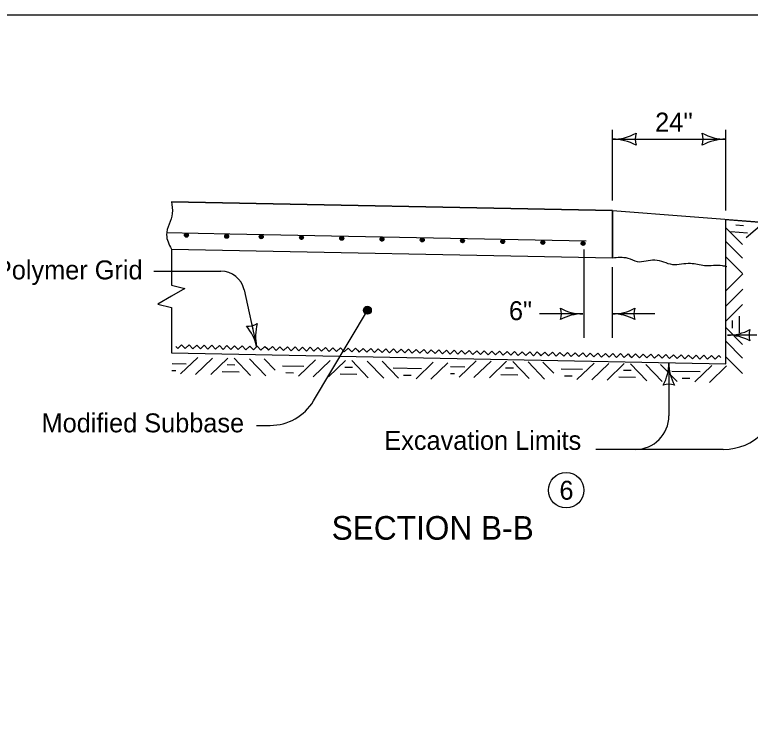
# Model space of a CAD drawing. Extents: x 9234 to 81668, y 5635 to 15999.
# Drawn here: x 18601 to 19223, y 9343 to 9944 of the extents above; entities that cross this region are included whole.
import ezdxf

# ---------------------------------------------------------------- set-up
doc = ezdxf.new("R2010")
doc.units = 0
for name, color, linetype in [('Level 61', 7, 'Continuous'), ('PS_CONST', 7, 'Continuous'), ('PS_DAWA', 7, 'Continuous'), ('PS_DIM', 7, 'Continuous'), ('PS_TEXT', 7, 'Continuous')]:
    doc.layers.add(name, color=color, linetype=linetype)

msp = doc.modelspace()

# ---------------------------------------------------------------- linework, layer by layer
at = {"layer": 'Level 61'}
msp.add_lwpolyline([(17332.52, 9944.02), (20467.53, 9944.02), (20467.53, 7924.02), (17332.52, 7924.02)], close=True, dxfattribs=at)
at = {"layer": 'PS_CONST'}
for p, q in [((18718.71, 9727.25), (18775.55, 9727.25)), ((18795.09, 9711.56), (18805.7, 9663.43)), ((18853.75, 9617.59), (18899.36, 9693.89)), ((19228.64, 9673.11), (19203.92, 9673.11)), ((19154.23, 9649.79), (19154.23, 9604.94)), ((18805.59, 9596.88), (18817.24, 9596.88)), ((19200.27, 9576.58), (19092.51, 9576.58))]:
    msp.add_line(p, q, dxfattribs=at)
msp.add_lwpolyline([(18899.08, 9691.17), (18900.2, 9691.67), (18901.94, 9692.21), (18902.27, 9693.97), (18902.03, 9695.52), (18900.92, 9696.95), (18899.27, 9696.8), (18897.53, 9696.56), (18896.69, 9695.17), (18896.54, 9693.7), (18897.57, 9691.79), (18898.84, 9691.63), (18900.58, 9692.08), (18902, 9693.18), (18901.96, 9694.84), (18900.85, 9696.17), (18899.29, 9696.31), (18897.54, 9695.97), (18897.28, 9695), (18896.93, 9693.82), (18897.75, 9692.38), (18899.01, 9692.42), (18900.47, 9692.65), (18901.51, 9693.46), (18900.98, 9694.91), (18899.89, 9695.75), (18898.43, 9695.8), (18898.06, 9695.02), (18897.6, 9694.13), (18898.31, 9692.98), (18899.39, 9692.72), (18900.35, 9693.23), (18900.42, 9694.3), (18899.91, 9695.07), (18898.93, 9695.33), (18898.45, 9694.93), (18898.18, 9694.34), (18898.69, 9693.48), (18899.38, 9693.3), (18900.04, 9693.71), (18899.93, 9694.29), (18899.43, 9694.67), (18898.76, 9694.64), (18898.77, 9694.16), (18899.36, 9693.89)], dxfattribs=at)
msp.add_circle((18899.34, 9694.21), 3.31, dxfattribs=at)
for centre, radius, start, end in [((18775.55, 9707.25), 20, 12.43134, 90), ((18798.45, 9696.33), 15.52, 264.68499, 300.15169), ((18766.46, 9654.79), 40.18, 12.41834, 40.49083), ((18844.93, 9672.07), 40.18, 164.34585, 192.41834), ((19203.92, 9713.29), 40.18, 270, 298.07249), ((19203.92, 9632.93), 40.18, 61.92751, 90), ((19237.6, 9673.11), 15.52, 162.26665, 197.73335), ((19114.05, 9649.79), 40.18, 331.92751, 360), ((19194.41, 9649.79), 40.18, 180, 208.07249), ((19154.23, 9616.11), 15.52, 72.26665, 107.73335), ((19200.28, 9623.84), 47.27, 270, 360), ((18817.24, 9639.42), 42.54, 270, 329.12488), ((19125.87, 9604.94), 28.36, 270, 360)]:
    msp.add_arc(centre, radius, start, end, dxfattribs=at)
at = {"layer": 'PS_DAWA'}
for p, q in [((19106.5, 9787.07), (19106.5, 9846.77)), ((19202.5, 9778.5), (19202.5, 9846.77)), ((19106.5, 9838.79), (19202.5, 9838.79)), ((19082.5, 9670.95), (19082.5, 9745.42)), ((19106.5, 9670.95), (19106.5, 9730.66)), ((19081.51, 9691.14), (19044.97, 9691.14)), ((19142.28, 9691.14), (19106.5, 9691.14))]:
    msp.add_line(p, q, dxfattribs=at)
for centre, radius, start, end in [((19106.5, 9881.29), 42.5, 270, 298.07249), ((19142.14, 9838.79), 16.42, 162.26665, 197.73335), ((19166.86, 9838.79), 16.42, 342.26665, 17.73335), ((19202.5, 9881.29), 42.5, 241.92751, 270), ((19106.5, 9796.29), 42.5, 61.92751, 90), ((19202.5, 9796.29), 42.5, 90, 118.07249), ((19047.82, 9691.14), 15.52, 342.26665, 17.73335), ((19081.51, 9731.31), 40.18, 241.92751, 270), ((19081.51, 9650.96), 40.18, 90, 118.07249), ((19106.5, 9731.31), 40.18, 270, 298.07249), ((19106.5, 9650.96), 40.18, 61.92751, 90), ((19140.19, 9691.14), 15.52, 162.26665, 197.73335)]:
    msp.add_arc(centre, radius, start, end, dxfattribs=at)
at = {"layer": 'PS_DIM'}
for p, q in [((19106.5, 9778.5), (18733.57, 9785.99)), ((18733.57, 9785.99), (19106.5, 9778.5)), ((19106.5, 9738.5), (19106.5, 9778.5)), ((19106.5, 9778.5), (19106.5, 9738.5)), ((19106.5, 9778.5), (19305.96, 9763.15)), ((19201.89, 9770.92), (19305.35, 9762.96)), ((19202.5, 9648.85), (19202.5, 9771.12)), ((19234.79, 9768.39), (19219.61, 9755.38)), ((18783.05, 9758.55), (18729.6, 9759.63)), ((19202.5, 9764.01), (19216.64, 9749.87)), ((19084.4, 9752.51), (18783.05, 9758.55)), ((19202.5, 9752.43), (19216.64, 9738.29)), ((18733.57, 9745.98), (19106.5, 9738.5)), ((18733.57, 9745.98), (19106.5, 9738.5)), ((18733.57, 9745.72), (18733.57, 9715.46)), ((19202.5, 9739.37), (19216.64, 9725.23)), ((19202.73, 9710.84), (19216.87, 9724.99)), ((18733.57, 9715.46), (18744.92, 9712.63)), ((18744.92, 9712.63), (18733.57, 9706.01)), ((19202.73, 9697.94), (19216.87, 9712.08)), ((18733.57, 9706.01), (18722.23, 9699.39)), ((18722.23, 9699.39), (18733.57, 9696.55)), ((18733.57, 9696.55), (18733.57, 9658.24)), ((19202.5, 9684.93), (19216.64, 9699.07)), ((18801.3, 9683.35), (18802.43, 9678.24)), ((19202.5, 9679.52), (19216.64, 9665.37)), ((19202.5, 9667.94), (19216.64, 9653.8)), ((18733.57, 9658.24), (19202.49, 9648.83)), ((18755.84, 9654.22), (18741.42, 9640.37)), ((18768.29, 9653.75), (18753.86, 9639.89)), ((18781.3, 9653.71), (18766.87, 9639.86)), ((18786.71, 9653.6), (18800.56, 9639.18)), ((18799.71, 9653.12), (18813.56, 9638.69)), ((18812.16, 9653.09), (18821.26, 9643.62)), ((19202.5, 9654.88), (19216.64, 9640.74)), ((18855.38, 9652.23), (18840.95, 9638.37)), ((18867.82, 9651.75), (18853.4, 9637.89)), ((18880.83, 9651.71), (18866.41, 9637.86)), ((18886.24, 9651.61), (18900.09, 9637.18)), ((18899.24, 9651.12), (18913.1, 9636.7)), ((18911.69, 9651.09), (18925.55, 9636.67)), ((18954.91, 9650.23), (18940.48, 9636.37)), ((18967.35, 9649.75), (18952.93, 9635.9)), ((18991.44, 9651.59), (18977.02, 9637.73)), ((19003.89, 9651.11), (18989.46, 9637.25)), ((19016.9, 9651.07), (19002.47, 9637.22)), ((19022.31, 9650.97), (19036.16, 9636.54)), ((19035.31, 9650.48), (19049.16, 9636.06)), ((19047.76, 9650.46), (19056.86, 9640.98)), ((19090.98, 9649.59), (19076.55, 9635.73)), ((19103.42, 9649.11), (19089, 9635.26)), ((19116.43, 9649.08), (19102.01, 9635.22)), ((19121.84, 9648.97), (19135.7, 9634.55)), ((19134.84, 9648.48), (19148.7, 9634.06)), ((19147.29, 9648.46), (19161.15, 9634.03)), ((19190.51, 9647.59), (19176.09, 9633.73)), ((19202.95, 9647.11), (19188.53, 9633.26))]:
    msp.add_line(p, q, dxfattribs=at)
for points in [[(19210.8, 9766.38), (19217.32, 9765.88)], [(18744.82, 9757.5), (18745.07, 9758.06), (18745.34, 9758.92), (18746.22, 9759.09), (18746.99, 9758.97), (18747.71, 9758.42), (18747.64, 9757.59), (18747.51, 9756.72), (18746.82, 9756.3), (18746.09, 9756.22), (18745.13, 9756.74), (18745.05, 9757.37), (18745.27, 9758.24), (18745.83, 9758.96), (18746.65, 9758.93), (18747.32, 9758.38), (18747.39, 9757.6), (18747.22, 9756.73), (18746.73, 9756.59), (18746.14, 9756.42), (18745.43, 9756.82), (18745.44, 9757.46), (18745.56, 9758.18), (18745.96, 9758.71), (18746.69, 9758.45), (18747.11, 9757.9), (18747.14, 9757.17), (18746.74, 9756.98), (18746.3, 9756.75), (18745.73, 9757.11), (18745.59, 9757.65), (18745.85, 9758.13), (18746.39, 9758.16), (18746.77, 9757.91), (18746.9, 9757.42), (18746.7, 9757.18), (18746.4, 9757.04), (18745.97, 9757.3), (18745.89, 9757.64), (18746.09, 9757.97), (18746.38, 9757.92), (18746.57, 9757.67), (18746.56, 9757.33), (18746.32, 9757.34), (18746.18, 9757.63)], [(19206.54, 9760.83), (19220.69, 9759.74)], [(18778.85, 9756.57), (18779.1, 9757.13), (18779.37, 9758), (18780.25, 9758.16), (18781.03, 9758.04), (18781.74, 9757.49), (18781.67, 9756.66), (18781.55, 9755.79), (18780.86, 9755.37), (18780.12, 9755.29), (18779.16, 9755.81), (18779.09, 9756.44), (18779.31, 9757.32), (18779.86, 9758.03), (18780.69, 9758), (18781.35, 9757.45), (18781.42, 9756.67), (18781.26, 9755.8), (18780.77, 9755.67), (18780.18, 9755.49), (18779.46, 9755.9), (18779.48, 9756.53), (18779.59, 9757.26), (18780, 9757.78), (18780.72, 9757.52), (18781.14, 9756.97), (18781.17, 9756.24), (18780.78, 9756.06), (18780.33, 9755.82), (18779.76, 9756.18), (18779.63, 9756.72), (18779.88, 9757.2), (18780.42, 9757.23), (18780.8, 9756.98), (18780.94, 9756.49), (18780.73, 9756.25), (18780.44, 9756.11), (18780.01, 9756.37), (18779.92, 9756.71), (18780.12, 9757.05), (18780.41, 9756.99), (18780.6, 9756.74), (18780.59, 9756.4), (18780.35, 9756.41), (18780.21, 9756.7)], [(18811.11, 9756.24), (18810.86, 9756.8), (18810.59, 9757.66), (18809.71, 9757.84), (18808.94, 9757.72), (18808.22, 9757.16), (18808.3, 9756.33), (18808.42, 9755.46), (18809.11, 9755.04), (18809.84, 9754.97), (18810.8, 9755.48), (18810.88, 9756.12), (18810.66, 9756.98), (18810.1, 9757.7), (18809.28, 9757.68), (18808.61, 9757.12), (18808.54, 9756.34), (18808.71, 9755.47), (18809.2, 9755.34), (18809.79, 9755.16), (18810.51, 9755.57), (18810.49, 9756.2), (18810.37, 9756.93), (18809.97, 9757.45), (18809.24, 9757.19), (18808.82, 9756.64), (18808.8, 9755.91), (18809.19, 9755.73), (18809.63, 9755.5), (18810.21, 9755.85), (18810.34, 9756.39), (18810.08, 9756.87), (18809.54, 9756.9), (18809.16, 9756.65), (18809.03, 9756.16), (18809.23, 9755.92), (18809.53, 9755.78), (18809.96, 9756.04), (18810.04, 9756.39), (18809.84, 9756.72), (18809.55, 9756.66), (18809.36, 9756.41), (18809.37, 9756.07), (18809.62, 9756.08), (18809.75, 9756.38)], [(18845.14, 9755.56), (18844.89, 9756.11), (18844.62, 9756.98), (18843.74, 9757.15), (18842.97, 9757.03), (18842.25, 9756.48), (18842.33, 9755.65), (18842.45, 9754.78), (18843.14, 9754.36), (18843.87, 9754.28), (18844.83, 9754.8), (18844.91, 9755.43), (18844.69, 9756.3), (18844.14, 9757.02), (18843.31, 9756.99), (18842.64, 9756.44), (18842.57, 9755.65), (18842.74, 9754.79), (18843.23, 9754.65), (18843.82, 9754.48), (18844.54, 9754.89), (18844.52, 9755.52), (18844.4, 9756.24), (18844, 9756.77), (18843.28, 9756.51), (18842.85, 9755.96), (18842.83, 9755.22), (18843.22, 9755.04), (18843.67, 9754.81), (18844.24, 9755.17), (18844.37, 9755.71), (18844.11, 9756.19), (18843.58, 9756.22), (18843.2, 9755.97), (18843.06, 9755.47), (18843.26, 9755.24), (18843.56, 9755.1), (18843.99, 9755.36), (18844.08, 9755.7), (18843.87, 9756.04), (18843.58, 9755.98), (18843.4, 9755.73), (18843.4, 9755.39), (18843.65, 9755.4), (18843.79, 9755.69)], [(18879.18, 9754.87), (18878.92, 9755.43), (18878.65, 9756.3), (18877.78, 9756.47), (18877, 9756.35), (18876.29, 9755.79), (18876.36, 9754.97), (18876.48, 9754.09), (18877.18, 9753.67), (18877.91, 9753.6), (18878.86, 9754.12), (18878.95, 9754.75), (18878.73, 9755.62), (18878.17, 9756.33), (18877.34, 9756.31), (18876.68, 9755.75), (18876.6, 9754.97), (18876.77, 9754.1), (18877.26, 9753.97), (18877.86, 9753.79), (18878.57, 9754.2), (18878.55, 9754.83), (18878.43, 9755.56), (18878.03, 9756.09), (18877.31, 9755.82), (18876.88, 9755.27), (18876.86, 9754.54), (18877.25, 9754.36), (18877.7, 9754.13), (18878.27, 9754.49), (18878.4, 9755.03), (18878.15, 9755.51), (18877.61, 9755.54), (18877.23, 9755.28), (18877.09, 9754.8), (18877.3, 9754.56), (18877.59, 9754.42), (18878.02, 9754.68), (18878.11, 9755.02), (18877.91, 9755.35), (18877.62, 9755.3), (18877.43, 9755.05), (18877.44, 9754.71), (18877.68, 9754.71), (18877.82, 9755.01)], [(18913.21, 9754.19), (18912.96, 9754.75), (18912.69, 9755.62), (18911.81, 9755.79), (18911.04, 9755.66), (18910.32, 9755.11), (18910.39, 9754.28), (18910.51, 9753.41), (18911.21, 9753), (18911.94, 9752.92), (18912.9, 9753.43), (18912.98, 9754.06), (18912.76, 9754.94), (18912.2, 9755.65), (18911.38, 9755.62), (18910.71, 9755.07), (18910.64, 9754.29), (18910.8, 9753.42), (18911.3, 9753.29), (18911.89, 9753.11), (18912.6, 9753.52), (18912.59, 9754.15), (18912.47, 9754.88), (18912.06, 9755.4), (18911.34, 9755.14), (18910.92, 9754.59), (18910.89, 9753.86), (18911.29, 9753.67), (18911.73, 9753.44), (18912.31, 9753.8), (18912.43, 9754.34), (18912.18, 9754.82), (18911.64, 9754.86), (18911.26, 9754.6), (18911.13, 9754.11), (18911.33, 9753.87), (18911.63, 9753.74), (18912.06, 9753.99), (18912.14, 9754.33), (18911.94, 9754.67), (18911.65, 9754.61), (18911.46, 9754.36), (18911.47, 9754.02), (18911.72, 9754.03), (18911.85, 9754.32)], [(18947.24, 9753.5), (18946.99, 9754.06), (18946.72, 9754.93), (18945.84, 9755.1), (18945.07, 9754.98), (18944.35, 9754.43), (18944.43, 9753.6), (18944.55, 9752.73), (18945.24, 9752.31), (18945.97, 9752.23), (18946.93, 9752.75), (18947.01, 9753.38), (18946.79, 9754.25), (18946.23, 9754.97), (18945.41, 9754.94), (18944.74, 9754.39), (18944.67, 9753.61), (18944.84, 9752.73), (18945.33, 9752.6), (18945.92, 9752.43), (18946.64, 9752.84), (18946.62, 9753.47), (18946.5, 9754.2), (18946.1, 9754.72), (18945.37, 9754.45), (18944.95, 9753.91), (18944.93, 9753.17), (18945.32, 9753), (18945.76, 9752.76), (18946.34, 9753.12), (18946.47, 9753.66), (18946.21, 9754.14), (18945.67, 9754.17), (18945.29, 9753.92), (18945.16, 9753.43), (18945.36, 9753.19), (18945.66, 9753.05), (18946.09, 9753.31), (18946.17, 9753.65), (18945.97, 9753.99), (18945.68, 9753.93), (18945.49, 9753.68), (18945.5, 9753.34), (18945.75, 9753.35), (18945.88, 9753.65)], [(18981.27, 9752.82), (18981.02, 9753.38), (18980.76, 9754.25), (18979.87, 9754.42), (18979.1, 9754.3), (18978.38, 9753.74), (18978.46, 9752.92), (18978.58, 9752.05), (18979.27, 9751.63), (18980.01, 9751.55), (18980.96, 9752.06), (18981.04, 9752.7), (18980.82, 9753.57), (18980.27, 9754.28), (18979.44, 9754.26), (18978.78, 9753.7), (18978.7, 9752.92), (18978.87, 9752.05), (18979.36, 9751.92), (18979.95, 9751.74), (18980.67, 9752.15), (18980.65, 9752.79), (18980.54, 9753.51), (18980.13, 9754.04), (18979.41, 9753.77), (18978.98, 9753.23), (18978.96, 9752.5), (18979.35, 9752.31), (18979.8, 9752.08), (18980.37, 9752.43), (18980.5, 9752.98), (18980.24, 9753.46), (18979.71, 9753.49), (18979.33, 9753.23), (18979.19, 9752.74), (18979.39, 9752.51), (18979.69, 9752.37), (18980.12, 9752.62), (18980.21, 9752.97), (18980.01, 9753.3), (18979.71, 9753.25), (18979.53, 9753), (18979.53, 9752.66), (18979.78, 9752.66), (18979.91, 9752.96)], [(19015.31, 9752.14), (19015.05, 9752.7), (19014.79, 9753.57), (19013.91, 9753.74), (19013.13, 9753.62), (19012.42, 9753.06), (19012.49, 9752.23), (19012.61, 9751.36), (19013.3, 9750.94), (19014.04, 9750.87), (19015, 9751.38), (19015.08, 9752.02), (19014.86, 9752.89), (19014.3, 9753.6), (19013.47, 9753.58), (19012.81, 9753.02), (19012.73, 9752.24), (19012.9, 9751.37), (19013.4, 9751.24), (19013.99, 9751.06), (19014.7, 9751.47), (19014.68, 9752.1), (19014.57, 9752.83), (19014.16, 9753.35), (19013.44, 9753.09), (19013.02, 9752.54), (19012.99, 9751.81), (19013.38, 9751.63), (19013.83, 9751.4), (19014.4, 9751.76), (19014.53, 9752.29), (19014.28, 9752.77), (19013.74, 9752.81), (19013.36, 9752.55), (19013.22, 9752.06), (19013.42, 9751.82), (19013.72, 9751.68), (19014.15, 9751.94), (19014.24, 9752.29), (19014.04, 9752.62), (19013.75, 9752.56), (19013.56, 9752.32), (19013.57, 9751.97), (19013.81, 9751.98), (19013.95, 9752.28)], [(19046.18, 9751.45), (19046.43, 9752.01), (19046.7, 9752.88), (19047.58, 9753.04), (19048.35, 9752.92), (19049.07, 9752.37), (19049, 9751.54), (19048.87, 9750.67), (19048.18, 9750.25), (19047.45, 9750.18), (19046.49, 9750.69), (19046.41, 9751.33), (19046.63, 9752.2), (19047.19, 9752.91), (19048.01, 9752.88), (19048.68, 9752.33), (19048.75, 9751.55), (19048.58, 9750.68), (19048.09, 9750.54), (19047.5, 9750.37), (19046.79, 9750.78), (19046.8, 9751.41), (19046.92, 9752.14), (19047.32, 9752.66), (19048.05, 9752.4), (19048.47, 9751.85), (19048.5, 9751.12), (19048.1, 9750.93), (19047.66, 9750.71), (19047.08, 9751.06), (19046.95, 9751.6), (19047.21, 9752.08), (19047.75, 9752.11), (19048.13, 9751.86), (19048.26, 9751.37), (19048.06, 9751.13), (19047.76, 9750.99), (19047.33, 9751.25), (19047.25, 9751.6), (19047.45, 9751.93), (19047.74, 9751.87), (19047.93, 9751.62), (19047.92, 9751.28), (19047.67, 9751.29), (19047.54, 9751.58)], [(19080.21, 9750.52), (19080.46, 9751.08), (19080.73, 9751.95), (19081.61, 9752.11), (19082.39, 9751.99), (19083.1, 9751.44), (19083.03, 9750.61), (19082.91, 9749.74), (19082.21, 9749.32), (19081.48, 9749.25), (19080.52, 9749.76), (19080.44, 9750.4), (19080.66, 9751.27), (19081.22, 9751.98), (19082.05, 9751.96), (19082.71, 9751.4), (19082.78, 9750.62), (19082.61, 9749.75), (19082.12, 9749.62), (19081.54, 9749.44), (19080.82, 9749.85), (19080.84, 9750.49), (19080.95, 9751.21), (19081.36, 9751.73), (19082.08, 9751.47), (19082.5, 9750.92), (19082.53, 9750.19), (19082.14, 9750.01), (19081.69, 9749.78), (19081.12, 9750.13), (19080.99, 9750.67), (19081.24, 9751.15), (19081.78, 9751.19), (19082.16, 9750.93), (19082.3, 9750.44), (19082.09, 9750.2), (19081.8, 9750.07), (19081.37, 9750.32), (19081.28, 9750.66), (19081.48, 9751), (19081.77, 9750.94), (19081.96, 9750.69), (19081.95, 9750.35), (19081.71, 9750.36), (19081.57, 9750.66)], [(19208, 9678.96), (19208, 9685.49)], [(19213.85, 9675.13), (19213.85, 9689.32)], [(18737.38, 9663.57), (18738.95, 9661.94), (18742.21, 9665.07), (18745.35, 9661.81), (18748.61, 9664.94), (18751.75, 9661.68), (18755.01, 9664.81), (18758.15, 9661.55), (18761.41, 9664.69), (18764.55, 9661.42), (18767.81, 9664.56), (18770.94, 9661.29), (18774.21, 9664.43), (18777.34, 9661.17), (18780.61, 9664.3), (18783.74, 9661.04), (18787.01, 9664.17), (18790.14, 9660.91), (18793.4, 9664.04), (18796.54, 9660.78), (18799.8, 9663.92), (18802.94, 9660.65), (18806.2, 9663.79), (18809.34, 9660.52), (18812.6, 9663.66), (18814.17, 9662.03)], [(18814.17, 9662.03), (18815.74, 9660.4), (18819, 9663.53), (18822.13, 9660.27), (18825.4, 9663.4), (18828.53, 9660.14), (18831.8, 9663.27), (18834.93, 9660.01), (18838.2, 9663.15), (18841.33, 9659.88), (18844.59, 9663.02), (18847.73, 9659.75), (18850.99, 9662.89), (18854.13, 9659.62), (18857.39, 9662.76), (18860.53, 9659.5), (18863.79, 9662.63), (18866.93, 9659.37), (18870.19, 9662.5), (18873.32, 9659.24), (18876.59, 9662.37), (18879.72, 9659.11), (18882.99, 9662.25), (18886.12, 9658.98), (18889.38, 9662.12), (18890.95, 9660.49)], [(18890.95, 9660.49), (18892.52, 9658.85), (18895.78, 9661.99), (18898.92, 9658.73), (18902.18, 9661.86), (18905.32, 9658.6), (18908.58, 9661.73), (18911.72, 9658.47), (18914.98, 9661.6), (18918.11, 9658.34), (18921.38, 9661.48), (18924.51, 9658.21), (18927.78, 9661.35), (18930.91, 9658.08), (18934.18, 9661.22), (18937.31, 9657.95), (18940.57, 9661.09), (18943.71, 9657.83), (18946.97, 9660.96), (18950.11, 9657.7), (18953.37, 9660.83), (18956.51, 9657.57), (18959.77, 9660.7), (18962.91, 9657.44), (18966.17, 9660.58), (18967.74, 9658.94)], [(18967.77, 9658.84), (18969.34, 9657.21), (18972.6, 9660.35), (18975.74, 9657.08), (18979, 9660.22), (18982.14, 9656.95), (18985.4, 9660.09), (18988.54, 9656.83), (18991.8, 9659.96), (18994.93, 9656.7), (18998.2, 9659.83), (19001.33, 9656.57), (19004.6, 9659.7), (19007.73, 9656.44), (19010.99, 9659.58), (19014.13, 9656.31), (19017.39, 9659.45), (19020.53, 9656.18), (19023.79, 9659.32), (19026.93, 9656.06), (19030.19, 9659.19), (19033.33, 9655.93), (19036.59, 9659.06), (19039.72, 9655.8), (19042.99, 9658.93), (19044.56, 9657.3)], [(19044.56, 9657.3), (19046.12, 9655.67), (19049.39, 9658.81), (19052.52, 9655.54), (19055.79, 9658.68), (19058.92, 9655.41), (19062.18, 9658.55), (19065.32, 9655.29), (19068.58, 9658.42), (19071.72, 9655.16), (19074.98, 9658.29), (19078.12, 9655.03), (19081.38, 9658.16), (19084.52, 9654.9), (19087.78, 9658.03), (19090.91, 9654.77), (19094.18, 9657.91), (19097.31, 9654.64), (19100.58, 9657.78), (19103.71, 9654.51), (19106.98, 9657.65), (19110.11, 9654.39), (19113.37, 9657.52), (19116.51, 9654.26), (19119.77, 9657.39), (19121.34, 9655.76)], [(19121.34, 9655.76), (19122.91, 9654.13), (19126.17, 9657.26), (19129.31, 9654), (19132.57, 9657.14), (19135.71, 9653.87), (19138.97, 9657.01), (19142.1, 9653.74), (19145.37, 9656.88), (19148.5, 9653.62), (19151.77, 9656.75), (19154.9, 9653.49), (19158.17, 9656.62), (19161.3, 9653.36), (19164.56, 9656.49), (19167.7, 9653.23), (19170.96, 9656.37), (19174.1, 9653.1), (19177.36, 9656.24), (19180.5, 9652.97), (19183.76, 9656.11), (19186.9, 9652.84), (19190.16, 9655.98), (19193.29, 9652.72), (19196.56, 9655.85), (19198.13, 9654.22)], [(18734.13, 9649.18), (18746.15, 9648.94)], [(18780.63, 9648.23), (18787.16, 9648.1)], [(18827.62, 9647.31), (18845.69, 9646.94)], [(18734.01, 9643.38), (18737.27, 9643.32)], [(18776.68, 9642.45), (18790.87, 9642.16)], [(18830.28, 9641.45), (18836.81, 9641.32)], [(18880.16, 9646.23), (18886.69, 9646.1)], [(18921.16, 9645.43), (18945.22, 9644.95)], [(18969.61, 9640.75), (18972.87, 9640.68)], [(18969.73, 9646.55), (18981.75, 9646.3)], [(19016.23, 9645.59), (19022.76, 9645.46)], [(19063.22, 9644.67), (19081.29, 9644.31)], [(19115.76, 9643.59), (19122.29, 9643.46)], [(19156.76, 9642.79), (19180.82, 9642.31)], [(18876.21, 9640.45), (18890.4, 9640.17)], [(18929.81, 9639.45), (18936.34, 9639.32)], [(19012.28, 9639.81), (19026.47, 9639.53)], [(19065.88, 9638.81), (19072.41, 9638.68)], [(19111.81, 9637.81), (19126, 9637.53)], [(19165.41, 9636.82), (19171.94, 9636.69)]]:
    msp.add_lwpolyline(points, dxfattribs=at)
for centre in [(18746.34, 9757.62), (18780.37, 9756.69), (18809.59, 9756.36), (18843.62, 9755.68), (18877.66, 9755), (18911.69, 9754.31), (18945.72, 9753.63), (18979.75, 9752.95), (19013.79, 9752.26), (19047.7, 9751.57), (19081.73, 9750.64)]:
    msp.add_circle(centre, 1.65, dxfattribs=at)
for points in [[(18733.57, 9785.99), (18734.39, 9775.97), (18729.51, 9757.93), (18733.57, 9745.98)], [(18733.57, 9785.99), (18734.39, 9775.97), (18729.51, 9757.93), (18733.57, 9745.98)], [(19106.5, 9738.5), (19119.45, 9738.29), (19127.58, 9735.42), (19142.4, 9736.85), (19157.23, 9733.02), (19172.53, 9733.98), (19184.49, 9732.07), (19199.31, 9732.07), (19203.14, 9731.11)]]:
    msp.add_spline(points, degree=3, dxfattribs=at)
at = {"layer": 'PS_TEXT'}
msp.add_circle((19067.44, 9542.06), 15, dxfattribs=at)

# ---------------------------------------------------------------- texts
at = {"layer": 'PS_CONST'}
for s, height, p in [('Polymer Grid', 16, (18584.38, 9720.31)), ('Modified Subbase', 16, (18623.84, 9591)), ('Excavation Limits', 16, (18913.67, 9576.21)), ('SECTION B-B', 20, (18869.09, 9500.24))]:
    msp.add_text(s, height=height, dxfattribs=at).set_placement(p)
at = {"layer": 'PS_DAWA'}
for s, p in [("24''", (19142.63, 9845.25)), ('6"', (19019.03, 9685.82))]:
    msp.add_text(s, height=16, dxfattribs=at).set_placement(p)
at = {"layer": 'PS_TEXT'}
msp.add_text('6', height=16, dxfattribs=at).set_placement((19061.73, 9534.06))

doc.saveas('drawing.dxf')
